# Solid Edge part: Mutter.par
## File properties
Sűrűség: 0,000 kg/m^3
Pontosság: 0,990
Author: ahadarics
Last saved by: ahadarics
Revision: 76
Username: ahadarics
Dokumentum tartalom típus: 0
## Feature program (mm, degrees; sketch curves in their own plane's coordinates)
base feature "unnamed BaseFeature 1"
thread "unnamed Thread 1"
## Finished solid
Body 1: solid body, 23 faces, 46 edges, 24 vertices.
  Faces by surface: cone 14, plane 8, cylinder 1
  Edges by curve: spline 24, circle 16, line 6
Bounding box of the edges (mm): 7.000 x 21.939 x 19.000, from (0, -10.9697, -9.5) to (7, 10.9697, 9.5).
Cylindrical faces by radius (mm): R5.3235 x1
Conical faces (half-angle, radius in mm at the cone's reference point): 60 deg R5.6618 x2, 60 deg R10.2348 x12
Planar faces by outward normal: +x 1, +z 1, -x 1, -z 1, oblique 4
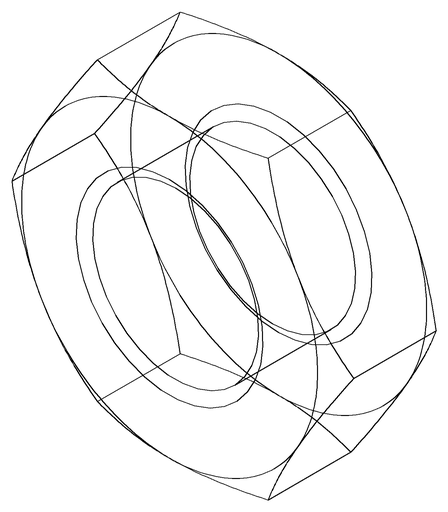
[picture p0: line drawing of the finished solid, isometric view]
